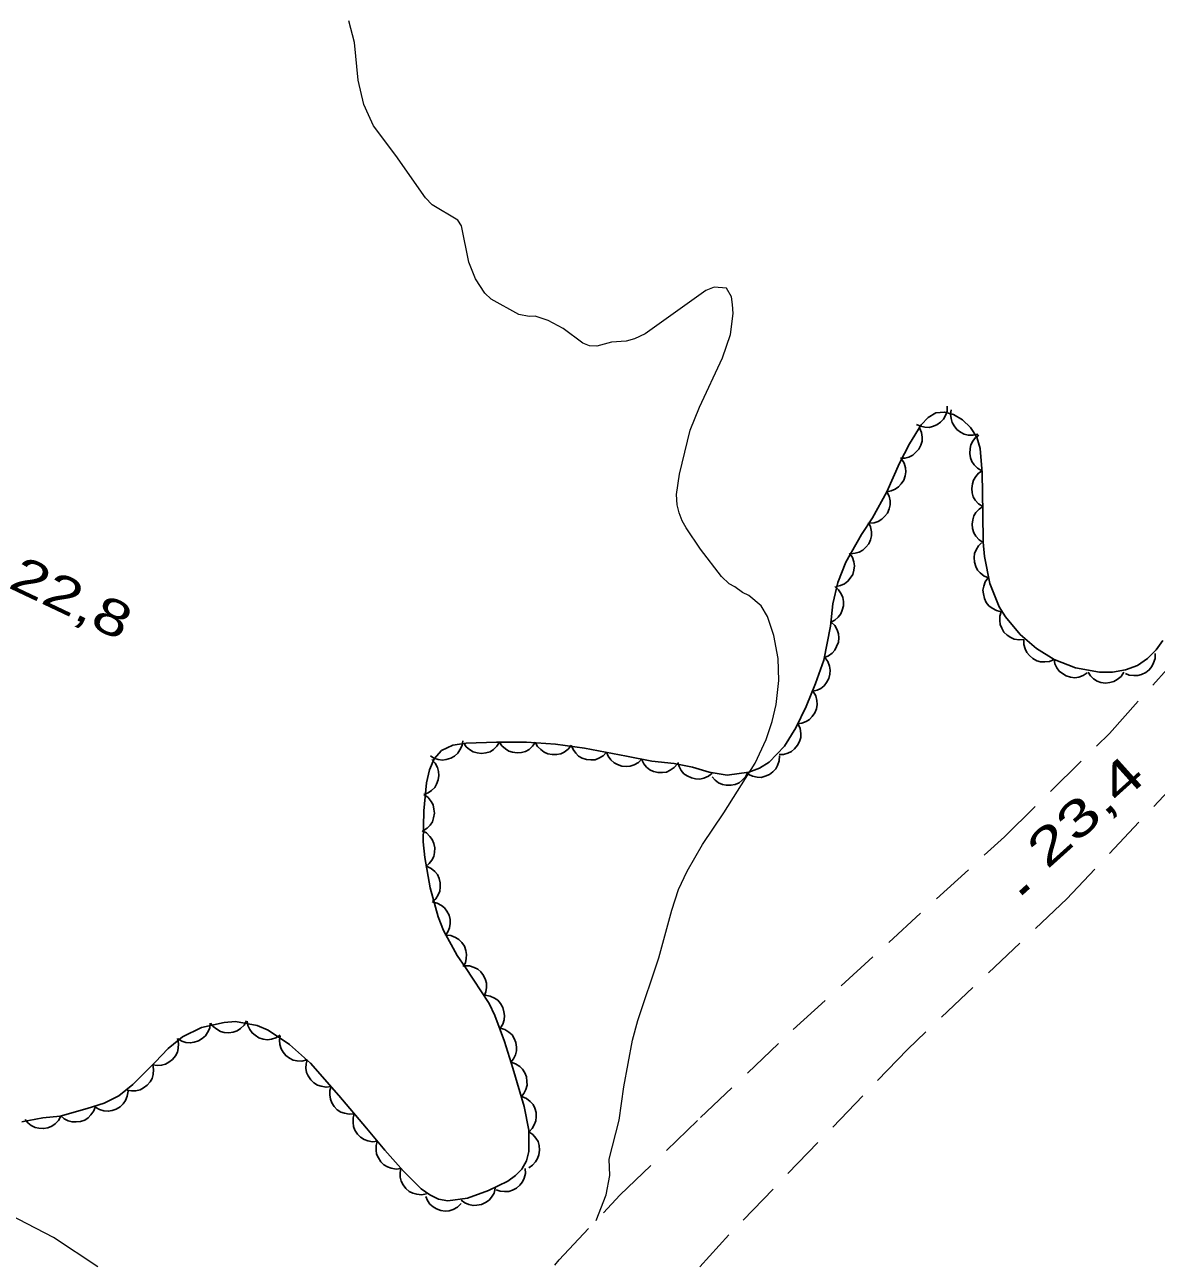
# Model space of a CAD drawing. Extents: x 356765 to 358572, y 5103174 to 5104650.
# Drawn here: x 357738.8 to 357786, y 5103637.9 to 5103689.6 of the extents above; entities that cross this region are included whole.
import ezdxf

# ---------------------------------------------------------------- set-up
doc = ezdxf.new("R2010")
doc.units = 0
doc.header["$LTSCALE"] = 0.6
for name, pattern in [('DOT_DASHED', [7.7, 5, -1.2, 0.3, -1.2]), ('LONG_DASHED', [7.5, 6, -1.5]), ('MEDIUM_DASHED', [4.5, 3, -1.5])]:
    doc.linetypes.add(name, pattern=pattern)
for name, color, linetype, lineweight in [('19', 7, 'Continuous', 13), ('2', 7, 'Continuous', 13), ('3', 7, 'Continuous', 140), ('44', 7, 'Continuous', 25)]:
    doc.layers.add(name, color=color, linetype=linetype, lineweight=lineweight)

msp = doc.modelspace()

# ---------------------------------------------------------------- linework, layer by layer
at = {"layer": '19', "linetype": 'MEDIUM_DASHED'}
for points in [[(357804.11, 5103692.49), (357803.18, 5103689.49), (357802.52, 5103685.58), (357801.73, 5103680.09), (357799.98, 5103676.05), (357799.47, 5103674.87), (357794.53, 5103667.37), (357789.01, 5103660.22), (357782.3, 5103653.09), (357775.64, 5103646.8), (357768.18, 5103639.05), (357761.58, 5103631.86), (357756.58, 5103624.59), (357752.29, 5103616.7), (357748.66, 5103609.09), (357747.46, 5103605.53), (357745.9, 5103600.84), (357743.2, 5103594.2), (357740.59, 5103586.65), (357739.01, 5103581.66), (357738.8, 5103580.59)], [(357732.38, 5103586.03), (357733.63, 5103587.26), (357740.14, 5103599.86), (357745.27, 5103609.99), (357750.21, 5103619.09), (357753.38, 5103624.96), (357757.55, 5103633.03), (357759.21, 5103635.68), (357761.09, 5103638.01), (357763.62, 5103640.71), (357766.99, 5103643.95), (357770.87, 5103647.63), (357779.69, 5103655.68), (357784.08, 5103660), (357790.96, 5103667.68), (357793.62, 5103671.63), (357796.87, 5103678.8), (357797.75, 5103682.08), (357798.44, 5103685.24), (357798.55, 5103687.17), (357797.98, 5103689.44), (357796.86, 5103691.88)]]:
    msp.add_lwpolyline(points, dxfattribs=at)
at = {"layer": '2', "linetype": 'LONG_DASHED'}
msp.add_lwpolyline([(357768.43, 5103666.12), (357768.19, 5103666.25), (357767.87, 5103666.55), (357766.99, 5103667.69), (357766.39, 5103668.59), (357766.22, 5103668.88), (357766.1, 5103669.21), (357766.02, 5103669.55), (357765.99, 5103669.97), (357766.11, 5103670.82), (357766.56, 5103672.66), (357766.95, 5103673.63), (357767.91, 5103675.69), (357768.25, 5103676.66), (357768.35, 5103677.54), (357768.33, 5103677.91), (357768.29, 5103678.23), (357768.08, 5103678.59), (357767.57, 5103678.63), (357767.22, 5103678.5), (357764.68, 5103676.68), (357764.24, 5103676.48), (357763.89, 5103676.38), (357763.27, 5103676.34), (357762.66, 5103676.17), (357762.36, 5103676.18), (357762.08, 5103676.3), (357761.25, 5103676.91), (357760.63, 5103677.24), (357760.09, 5103677.42), (357759.84, 5103677.41), (357759.41, 5103677.49), (357758.25, 5103678.13), (357757.98, 5103678.38), (357757.6, 5103678.99), (357757.31, 5103679.68), (357757.01, 5103681.19), (357756.86, 5103681.44), (357755.79, 5103682.07), (357755.51, 5103682.36), (357754.27, 5103684.13), (357753.33, 5103685.38), (357753.12, 5103685.83), (357752.93, 5103686.26), (357752.69, 5103687.28), (357752.54, 5103688.86), (357752.3, 5103689.76)], dxfattribs=at)
at = {"layer": '2'}
for points in [[(357762.63, 5103639.66), (357763.05, 5103640.73), (357763.21, 5103641.53), (357763.18, 5103642.21), (357763.59, 5103643.84), (357763.79, 5103645.24), (357764.15, 5103647.18), (357764.37, 5103648.01), (357765.25, 5103650.63), (357765.79, 5103652.62), (357766.07, 5103653.48), (357766.44, 5103654.24), (357767.07, 5103655.36), (357767.97, 5103656.68), (357769.28, 5103658.76), (357769.74, 5103659.74), (357769.99, 5103660.49), (357770.16, 5103661.21), (357770.26, 5103662.21), (357770.23, 5103663.13), (357770.06, 5103664.09), (357769.79, 5103664.88), (357769.53, 5103665.33), (357769.01, 5103665.76), (357768.74, 5103665.88), (357768.43, 5103666.12)], [(357741.82, 5103637.72), (357739.97, 5103638.95), (357737.76, 5103640.09)]]:
    msp.add_lwpolyline(points, dxfattribs=at)
at = {"layer": '3'}
msp.add_line((357780.38, 5103653.33), (357780.68, 5103653.6), dxfattribs=at)
at = {"layer": '44'}
for points in [[(357777.3, 5103673.67), (357777.29, 5103673.46), (357777.22, 5103673.27), (357777.14, 5103673.12), (357777.02, 5103673), (357776.87, 5103672.89), (357776.69, 5103672.82), (357776.54, 5103672.78), (357776.36, 5103672.79), (357776.18, 5103672.83), (357776.02, 5103672.9)], [(357778.58, 5103672.5), (357778.37, 5103672.45), (357778.17, 5103672.46), (357778.01, 5103672.5), (357777.85, 5103672.58), (357777.7, 5103672.69), (357777.59, 5103672.84), (357777.5, 5103672.98), (357777.46, 5103673.15), (357777.44, 5103673.33), (357777.47, 5103673.51)], [(357776.14, 5103672.76), (357776.22, 5103672.57), (357776.25, 5103672.37), (357776.25, 5103672.2), (357776.19, 5103672.04), (357776.11, 5103671.87), (357775.98, 5103671.73), (357775.86, 5103671.62), (357775.7, 5103671.54), (357775.53, 5103671.49), (357775.35, 5103671.49)], [(357778.75, 5103670.97), (357778.57, 5103671.07), (357778.43, 5103671.21), (357778.33, 5103671.35), (357778.27, 5103671.51), (357778.24, 5103671.69), (357778.25, 5103671.89), (357778.28, 5103672.05), (357778.37, 5103672.2), (357778.48, 5103672.35), (357778.62, 5103672.46)], [(357775.39, 5103671.46), (357775.5, 5103671.28), (357775.55, 5103671.09), (357775.57, 5103670.92), (357775.54, 5103670.75), (357775.48, 5103670.58), (357775.37, 5103670.42), (357775.27, 5103670.29), (357775.12, 5103670.2), (357774.95, 5103670.13), (357774.77, 5103670.09)], [(357778.78, 5103669.47), (357778.6, 5103669.58), (357778.47, 5103669.74), (357778.38, 5103669.88), (357778.34, 5103670.05), (357778.32, 5103670.23), (357778.35, 5103670.42), (357778.39, 5103670.58), (357778.49, 5103670.73), (357778.61, 5103670.86), (357778.76, 5103670.97)], [(357774.77, 5103670.09), (357774.87, 5103669.91), (357774.91, 5103669.71), (357774.91, 5103669.54), (357774.87, 5103669.37), (357774.8, 5103669.2), (357774.68, 5103669.05), (357774.57, 5103668.94), (357774.41, 5103668.85), (357774.24, 5103668.79), (357774.06, 5103668.78)], [(357778.8, 5103667.97), (357778.63, 5103668.08), (357778.49, 5103668.24), (357778.41, 5103668.38), (357778.36, 5103668.55), (357778.34, 5103668.73), (357778.37, 5103668.92), (357778.41, 5103669.08), (357778.5, 5103669.23), (357778.63, 5103669.36), (357778.78, 5103669.47)], [(357774.01, 5103668.81), (357774.1, 5103668.62), (357774.13, 5103668.42), (357774.14, 5103668.25), (357774.09, 5103668.08), (357774.02, 5103667.92), (357773.9, 5103667.77), (357773.78, 5103667.65), (357773.62, 5103667.57), (357773.45, 5103667.52), (357773.27, 5103667.5)], [(357779.03, 5103666.49), (357778.84, 5103666.57), (357778.68, 5103666.7), (357778.57, 5103666.82), (357778.49, 5103666.97), (357778.44, 5103667.15), (357778.43, 5103667.34), (357778.44, 5103667.51), (357778.51, 5103667.67), (357778.61, 5103667.83), (357778.73, 5103667.96)], [(357773.22, 5103667.52), (357773.34, 5103667.35), (357773.4, 5103667.16), (357773.42, 5103666.99), (357773.4, 5103666.82), (357773.35, 5103666.64), (357773.25, 5103666.48), (357773.15, 5103666.35), (357773.01, 5103666.25), (357772.84, 5103666.17), (357772.66, 5103666.13)], [(357779.55, 5103665.08), (357779.35, 5103665.13), (357779.17, 5103665.23), (357779.04, 5103665.33), (357778.93, 5103665.47), (357778.85, 5103665.63), (357778.81, 5103665.82), (357778.79, 5103665.98), (357778.83, 5103666.15), (357778.89, 5103666.33), (357778.99, 5103666.48)], [(357772.6, 5103666.14), (357772.76, 5103666), (357772.87, 5103665.83), (357772.94, 5103665.68), (357772.97, 5103665.51), (357772.96, 5103665.33), (357772.91, 5103665.14), (357772.85, 5103664.99), (357772.74, 5103664.85), (357772.6, 5103664.73), (357772.44, 5103664.65)], [(357780.51, 5103663.92), (357780.3, 5103663.9), (357780.1, 5103663.94), (357779.95, 5103664), (357779.8, 5103664.1), (357779.67, 5103664.23), (357779.58, 5103664.39), (357779.51, 5103664.54), (357779.49, 5103664.72), (357779.5, 5103664.9), (357779.55, 5103665.08)], [(357772.45, 5103664.65), (357772.6, 5103664.5), (357772.7, 5103664.32), (357772.75, 5103664.16), (357772.77, 5103663.99), (357772.75, 5103663.81), (357772.68, 5103663.63), (357772.61, 5103663.48), (357772.49, 5103663.35), (357772.34, 5103663.24), (357772.17, 5103663.17)], [(357781.76, 5103663.09), (357781.57, 5103663), (357781.37, 5103662.98), (357781.2, 5103662.98), (357781.04, 5103663.03), (357780.87, 5103663.12), (357780.73, 5103663.25), (357780.62, 5103663.37), (357780.55, 5103663.53), (357780.5, 5103663.71), (357780.5, 5103663.89)], [(357785.98, 5103663.34), (357785.98, 5103663.13), (357785.92, 5103662.94), (357785.85, 5103662.79), (357785.74, 5103662.65), (357785.59, 5103662.54), (357785.42, 5103662.46), (357785.26, 5103662.41), (357785.09, 5103662.41), (357784.9, 5103662.43), (357784.74, 5103662.5)], [(357772.19, 5103663.17), (357772.31, 5103663), (357772.38, 5103662.81), (357772.41, 5103662.64), (357772.4, 5103662.47), (357772.35, 5103662.29), (357772.26, 5103662.12), (357772.16, 5103661.99), (357772.02, 5103661.88), (357771.86, 5103661.8), (357771.68, 5103661.76)], [(357783.15, 5103662.53), (357782.98, 5103662.41), (357782.79, 5103662.35), (357782.63, 5103662.32), (357782.45, 5103662.34), (357782.27, 5103662.4), (357782.11, 5103662.5), (357781.98, 5103662.6), (357781.88, 5103662.74), (357781.8, 5103662.91), (357781.76, 5103663.08)], [(357784.68, 5103662.55), (357784.56, 5103662.38), (357784.4, 5103662.25), (357784.26, 5103662.16), (357784.09, 5103662.12), (357783.91, 5103662.1), (357783.72, 5103662.13), (357783.56, 5103662.18), (357783.41, 5103662.28), (357783.28, 5103662.4), (357783.18, 5103662.55)], [(357771.7, 5103661.75), (357771.81, 5103661.57), (357771.85, 5103661.37), (357771.87, 5103661.2), (357771.84, 5103661.03), (357771.77, 5103660.86), (357771.66, 5103660.7), (357771.55, 5103660.58), (357771.4, 5103660.49), (357771.23, 5103660.42), (357771.05, 5103660.4)], [(357771.07, 5103660.39), (357771.15, 5103660.2), (357771.18, 5103659.99), (357771.18, 5103659.83), (357771.13, 5103659.66), (357771.05, 5103659.5), (357770.92, 5103659.35), (357770.8, 5103659.24), (357770.64, 5103659.17), (357770.46, 5103659.11), (357770.28, 5103659.11)], [(357757.07, 5103659.69), (357757.03, 5103659.49), (357756.94, 5103659.31), (357756.85, 5103659.17), (357756.72, 5103659.05), (357756.56, 5103658.96), (357756.37, 5103658.91), (357756.21, 5103658.88), (357756.04, 5103658.91), (357755.86, 5103658.97), (357755.71, 5103659.06)], [(357758.6, 5103659.63), (357758.49, 5103659.46), (357758.34, 5103659.32), (357758.2, 5103659.23), (357758.03, 5103659.18), (357757.85, 5103659.16), (357757.66, 5103659.19), (357757.5, 5103659.23), (357757.35, 5103659.32), (357757.21, 5103659.44), (357757.1, 5103659.59)], [(357760.1, 5103659.63), (357759.98, 5103659.46), (357759.83, 5103659.33), (357759.68, 5103659.24), (357759.51, 5103659.2), (357759.33, 5103659.18), (357759.14, 5103659.21), (357758.98, 5103659.26), (357758.84, 5103659.36), (357758.7, 5103659.48), (357758.6, 5103659.63)], [(357761.6, 5103659.51), (357761.47, 5103659.34), (357761.3, 5103659.22), (357761.16, 5103659.15), (357760.98, 5103659.11), (357760.8, 5103659.11), (357760.61, 5103659.15), (357760.46, 5103659.21), (357760.32, 5103659.32), (357760.19, 5103659.45), (357760.1, 5103659.61)], [(357763.07, 5103659.21), (357762.92, 5103659.06), (357762.74, 5103658.96), (357762.59, 5103658.9), (357762.41, 5103658.89), (357762.23, 5103658.91), (357762.05, 5103658.97), (357761.9, 5103659.05), (357761.78, 5103659.17), (357761.67, 5103659.32), (357761.6, 5103659.48)], [(357764.54, 5103658.93), (357764.4, 5103658.78), (357764.22, 5103658.68), (357764.06, 5103658.63), (357763.89, 5103658.61), (357763.71, 5103658.63), (357763.53, 5103658.7), (357763.38, 5103658.77), (357763.25, 5103658.89), (357763.14, 5103659.04), (357763.07, 5103659.21)], [(357755.77, 5103658.91), (357755.91, 5103658.75), (357756, 5103658.57), (357756.05, 5103658.41), (357756.06, 5103658.24), (357756.04, 5103658.06), (357755.96, 5103657.88), (357755.89, 5103657.74), (357755.76, 5103657.61), (357755.61, 5103657.51), (357755.44, 5103657.44)], [(357766.03, 5103658.73), (357765.89, 5103658.57), (357765.72, 5103658.46), (357765.57, 5103658.38), (357765.4, 5103658.36), (357765.22, 5103658.36), (357765.03, 5103658.41), (357764.88, 5103658.47), (357764.74, 5103658.59), (357764.62, 5103658.73), (357764.54, 5103658.89)], [(357767.48, 5103658.34), (357767.32, 5103658.21), (357767.13, 5103658.13), (357766.97, 5103658.09), (357766.79, 5103658.1), (357766.61, 5103658.14), (357766.44, 5103658.22), (357766.3, 5103658.31), (357766.19, 5103658.45), (357766.1, 5103658.61), (357766.04, 5103658.78)], [(357770.29, 5103659.06), (357770.28, 5103658.85), (357770.21, 5103658.66), (357770.14, 5103658.52), (357770.02, 5103658.39), (357769.87, 5103658.28), (357769.69, 5103658.21), (357769.53, 5103658.16), (357769.36, 5103658.17), (357769.17, 5103658.21), (357769.01, 5103658.28)], [(357768.97, 5103658.37), (357768.87, 5103658.19), (357768.73, 5103658.04), (357768.61, 5103657.94), (357768.44, 5103657.87), (357768.26, 5103657.83), (357768.07, 5103657.84), (357767.91, 5103657.86), (357767.75, 5103657.93), (357767.6, 5103658.04), (357767.48, 5103658.18)], [(357755.44, 5103657.44), (357755.61, 5103657.32), (357755.74, 5103657.16), (357755.82, 5103657.01), (357755.86, 5103656.84), (357755.88, 5103656.66), (357755.84, 5103656.47), (357755.8, 5103656.31), (357755.7, 5103656.17), (357755.57, 5103656.04), (357755.42, 5103655.94)], [(357755.36, 5103655.93), (357755.54, 5103655.84), (357755.69, 5103655.69), (357755.79, 5103655.56), (357755.85, 5103655.4), (357755.89, 5103655.22), (357755.88, 5103655.02), (357755.85, 5103654.86), (357755.77, 5103654.71), (357755.66, 5103654.56), (357755.52, 5103654.44)], [(357755.54, 5103654.45), (357755.74, 5103654.36), (357755.89, 5103654.23), (357756, 5103654.1), (357756.07, 5103653.94), (357756.12, 5103653.76), (357756.12, 5103653.57), (357756.1, 5103653.41), (357756.03, 5103653.25), (357755.93, 5103653.09), (357755.8, 5103652.97)], [(357755.79, 5103652.96), (357755.99, 5103652.91), (357756.17, 5103652.81), (357756.3, 5103652.71), (357756.4, 5103652.57), (357756.49, 5103652.41), (357756.53, 5103652.22), (357756.54, 5103652.06), (357756.51, 5103651.88), (357756.44, 5103651.71), (357756.34, 5103651.56)], [(357756.36, 5103651.57), (357756.57, 5103651.55), (357756.76, 5103651.48), (357756.9, 5103651.39), (357757.02, 5103651.27), (357757.13, 5103651.11), (357757.19, 5103650.93), (357757.22, 5103650.77), (357757.21, 5103650.6), (357757.17, 5103650.42), (357757.08, 5103650.26)], [(357757.13, 5103650.29), (357757.34, 5103650.29), (357757.54, 5103650.22), (357757.69, 5103650.15), (357757.82, 5103650.04), (357757.93, 5103649.89), (357758.01, 5103649.71), (357758.06, 5103649.56), (357758.06, 5103649.38), (357758.02, 5103649.2), (357757.95, 5103649.03)], [(357758, 5103649.06), (357758.21, 5103649.03), (357758.39, 5103648.94), (357758.53, 5103648.85), (357758.64, 5103648.71), (357758.73, 5103648.55), (357758.78, 5103648.37), (357758.81, 5103648.21), (357758.79, 5103648.03), (357758.73, 5103647.86), (357758.64, 5103647.7)], [(357746.51, 5103647.9), (357746.49, 5103647.69), (357746.4, 5103647.51), (357746.31, 5103647.37), (357746.18, 5103647.25), (357746.02, 5103647.16), (357745.84, 5103647.1), (357745.68, 5103647.07), (357745.5, 5103647.09), (357745.33, 5103647.15), (357745.17, 5103647.24)], [(357748.03, 5103647.99), (357747.93, 5103647.81), (357747.78, 5103647.67), (357747.64, 5103647.58), (357747.47, 5103647.52), (357747.29, 5103647.49), (357747.1, 5103647.51), (357746.94, 5103647.55), (357746.79, 5103647.64), (357746.64, 5103647.75), (357746.53, 5103647.9)], [(357749.44, 5103647.4), (357749.26, 5103647.28), (357749.07, 5103647.23), (357748.9, 5103647.2), (357748.73, 5103647.23), (357748.55, 5103647.28), (357748.39, 5103647.39), (357748.26, 5103647.49), (357748.17, 5103647.63), (357748.09, 5103647.8), (357748.05, 5103647.98)], [(357745.15, 5103647.25), (357745.19, 5103647.04), (357745.18, 5103646.84), (357745.14, 5103646.68), (357745.06, 5103646.53), (357744.94, 5103646.38), (357744.79, 5103646.27), (357744.65, 5103646.18), (357744.48, 5103646.14), (357744.29, 5103646.13), (357744.11, 5103646.16)], [(357750.55, 5103646.36), (357750.34, 5103646.31), (357750.14, 5103646.32), (357749.98, 5103646.35), (357749.82, 5103646.43), (357749.67, 5103646.54), (357749.56, 5103646.69), (357749.47, 5103646.83), (357749.42, 5103647), (357749.41, 5103647.18), (357749.43, 5103647.36)], [(357758.62, 5103647.69), (357758.82, 5103647.63), (357758.99, 5103647.52), (357759.12, 5103647.41), (357759.21, 5103647.26), (357759.28, 5103647.09), (357759.31, 5103646.9), (357759.31, 5103646.74), (357759.26, 5103646.57), (357759.18, 5103646.4), (357759.07, 5103646.26)], [(357751.56, 5103645.25), (357751.35, 5103645.22), (357751.15, 5103645.26), (357750.99, 5103645.31), (357750.84, 5103645.4), (357750.71, 5103645.53), (357750.61, 5103645.69), (357750.54, 5103645.84), (357750.51, 5103646.01), (357750.52, 5103646.2), (357750.56, 5103646.37)], [(357759.08, 5103646.26), (357759.27, 5103646.2), (357759.44, 5103646.08), (357759.56, 5103645.97), (357759.66, 5103645.82), (357759.72, 5103645.65), (357759.74, 5103645.46), (357759.75, 5103645.3), (357759.7, 5103645.13), (357759.61, 5103644.96), (357759.5, 5103644.82)], [(357744.11, 5103646.16), (357744.15, 5103645.96), (357744.13, 5103645.75), (357744.09, 5103645.59), (357744, 5103645.44), (357743.88, 5103645.3), (357743.73, 5103645.19), (357743.59, 5103645.11), (357743.41, 5103645.07), (357743.23, 5103645.07), (357743.05, 5103645.1)], [(357752.53, 5103644.11), (357752.32, 5103644.09), (357752.12, 5103644.13), (357751.97, 5103644.18), (357751.82, 5103644.28), (357751.69, 5103644.41), (357751.59, 5103644.57), (357751.53, 5103644.72), (357751.51, 5103644.9), (357751.51, 5103645.08), (357751.56, 5103645.25)], [(357743.08, 5103645.05), (357743.05, 5103644.84), (357742.97, 5103644.66), (357742.88, 5103644.52), (357742.75, 5103644.4), (357742.59, 5103644.3), (357742.41, 5103644.25), (357742.25, 5103644.22), (357742.07, 5103644.24), (357741.89, 5103644.29), (357741.74, 5103644.38)], [(357759.53, 5103644.83), (357759.73, 5103644.75), (357759.88, 5103644.62), (357760, 5103644.5), (357760.07, 5103644.34), (357760.13, 5103644.17), (357760.13, 5103643.98), (357760.12, 5103643.81), (357760.05, 5103643.65), (357759.96, 5103643.49), (357759.83, 5103643.36)], [(357741.72, 5103644.43), (357741.65, 5103644.23), (357741.53, 5103644.06), (357741.42, 5103643.94), (357741.27, 5103643.85), (357741.1, 5103643.79), (357740.91, 5103643.77), (357740.74, 5103643.77), (357740.58, 5103643.82), (357740.41, 5103643.9), (357740.27, 5103644.02)], [(357740.27, 5103644.01), (357740.17, 5103643.83), (357740.03, 5103643.69), (357739.9, 5103643.59), (357739.73, 5103643.53), (357739.55, 5103643.49), (357739.36, 5103643.51), (357739.2, 5103643.54), (357739.04, 5103643.62), (357738.9, 5103643.73), (357738.78, 5103643.87)], [(357753.5, 5103642.97), (357753.29, 5103642.94), (357753.09, 5103642.98), (357752.94, 5103643.03), (357752.79, 5103643.13), (357752.66, 5103643.26), (357752.56, 5103643.43), (357752.5, 5103643.58), (357752.48, 5103643.75), (357752.48, 5103643.94), (357752.53, 5103644.11)], [(357759.82, 5103643.36), (357759.99, 5103643.24), (357760.12, 5103643.09), (357760.21, 5103642.95), (357760.25, 5103642.78), (357760.27, 5103642.59), (357760.24, 5103642.4), (357760.19, 5103642.25), (357760.1, 5103642.1), (357759.97, 5103641.96), (357759.82, 5103641.86)], [(357754.48, 5103641.83), (357754.28, 5103641.8), (357754.07, 5103641.84), (357753.92, 5103641.89), (357753.77, 5103641.98), (357753.64, 5103642.11), (357753.54, 5103642.27), (357753.46, 5103642.42), (357753.44, 5103642.59), (357753.44, 5103642.78), (357753.49, 5103642.95)], [(357755.54, 5103640.77), (357755.34, 5103640.73), (357755.14, 5103640.75), (357754.97, 5103640.79), (357754.82, 5103640.87), (357754.68, 5103640.99), (357754.57, 5103641.15), (357754.49, 5103641.29), (357754.45, 5103641.46), (357754.44, 5103641.65), (357754.47, 5103641.82)], [(357759.67, 5103641.82), (357759.68, 5103641.61), (357759.63, 5103641.42), (357759.56, 5103641.27), (357759.45, 5103641.13), (357759.31, 5103641.01), (357759.14, 5103640.92), (357758.99, 5103640.87), (357758.81, 5103640.86), (357758.63, 5103640.88), (357758.46, 5103640.94)], [(357756.99, 5103640.36), (357756.84, 5103640.21), (357756.66, 5103640.12), (357756.5, 5103640.06), (357756.32, 5103640.05), (357756.14, 5103640.07), (357755.96, 5103640.14), (357755.82, 5103640.22), (357755.69, 5103640.34), (357755.59, 5103640.49), (357755.52, 5103640.66)], [(357758.42, 5103641), (357758.37, 5103640.8), (357758.26, 5103640.63), (357758.16, 5103640.5), (357758.01, 5103640.4), (357757.84, 5103640.32), (357757.65, 5103640.29), (357757.49, 5103640.28), (357757.32, 5103640.32), (357757.15, 5103640.39), (357757, 5103640.5)]]:
    msp.add_lwpolyline(points, dxfattribs=at)
at = {"layer": '44', "linetype": 'DOT_DASHED'}
for points in [[(357786.3, 5103663.88), (357786.02, 5103663.49), (357785.67, 5103663.13), (357785.24, 5103662.84), (357784.74, 5103662.65), (357784.2, 5103662.55), (357783.66, 5103662.55), (357782.65, 5103662.73), (357781.77, 5103663.08), (357781.03, 5103663.55), (357780.34, 5103664.13), (357779.73, 5103664.86), (357779.47, 5103665.29), (357779.08, 5103666.26), (357778.85, 5103667.38), (357778.8, 5103667.98), (357778.78, 5103669.2), (357778.76, 5103670.88), (357778.67, 5103671.9), (357778.53, 5103672.37), (357778.27, 5103672.78), (357777.93, 5103673.09), (357777.56, 5103673.32), (357777.18, 5103673.42), (357776.82, 5103673.38), (357776.5, 5103673.19), (357776.21, 5103672.88), (357775.72, 5103672.09), (357775.31, 5103671.29), (357774.77, 5103670.09), (357774.18, 5103669), (357773.72, 5103668.3), (357773.07, 5103667.15), (357772.73, 5103666.3), (357772.52, 5103665.41), (357772.42, 5103664.48), (357772.15, 5103663.05), (357771.8, 5103662.08), (357771.4, 5103661.12), (357770.97, 5103660.23), (357770.5, 5103659.46), (357769.86, 5103658.8), (357769.45, 5103658.55), (357769.01, 5103658.38), (357768.11, 5103658.26), (357767.35, 5103658.38), (357766.66, 5103658.59), (357765.89, 5103658.74), (357764.96, 5103658.84), (357763.9, 5103659.05), (357762.14, 5103659.38), (357760.94, 5103659.55), (357759.72, 5103659.63), (357758.47, 5103659.63), (357757.21, 5103659.59), (357756.65, 5103659.5), (357756.18, 5103659.28), (357755.87, 5103658.93), (357755.67, 5103658.47), (357755.55, 5103657.94), (357755.43, 5103656.76), (357755.41, 5103655.47), (357755.48, 5103654.82), (357755.7, 5103653.55), (357756.03, 5103652.34), (357756.26, 5103651.76), (357756.83, 5103650.72), (357757.18, 5103650.22), (357758.16, 5103648.72), (357758.4, 5103648.21), (357758.8, 5103647.13), (357759.15, 5103646.01), (357759.62, 5103644.41), (357759.82, 5103643.42), (357759.82, 5103642.53), (357759.72, 5103642.15), (357759.53, 5103641.8), (357759.27, 5103641.53), (357758.94, 5103641.29), (357758.13, 5103640.9), (357757.26, 5103640.59), (357756.44, 5103640.47), (357756.05, 5103640.55), (357755.68, 5103640.72), (357755.33, 5103640.98), (357754.59, 5103641.71), (357753.81, 5103642.59)], [(357753.81, 5103642.59), (357753.04, 5103643.51), (357751.88, 5103644.88), (357750.7, 5103646.22), (357749.83, 5103647), (357748.93, 5103647.61), (357748.48, 5103647.8), (357747.57, 5103647.96), (357747.09, 5103647.93), (357746.15, 5103647.72), (357745.36, 5103647.33), (357744.76, 5103646.84), (357744.21, 5103646.26), (357743.28, 5103645.33), (357742.7, 5103644.86), (357742.08, 5103644.55), (357741.37, 5103644.33), (357740.24, 5103644.01), (357739.52, 5103643.94), (357738.64, 5103643.78)]]:
    msp.add_lwpolyline(points, dxfattribs=at)

# ---------------------------------------------------------------- texts
at = {"layer": '3'}
for s, rotation, width, p in [('22,8   ', 334.619, 1.35, (357738.02, 5103666.11)), ('23,4   ', 41.983, 1.45, (357781.47, 5103654.29))]:
    msp.add_text(s, height=1.5, rotation=rotation, dxfattribs=dict(at, width=width)).set_placement(p)

doc.saveas('drawing.dxf')
